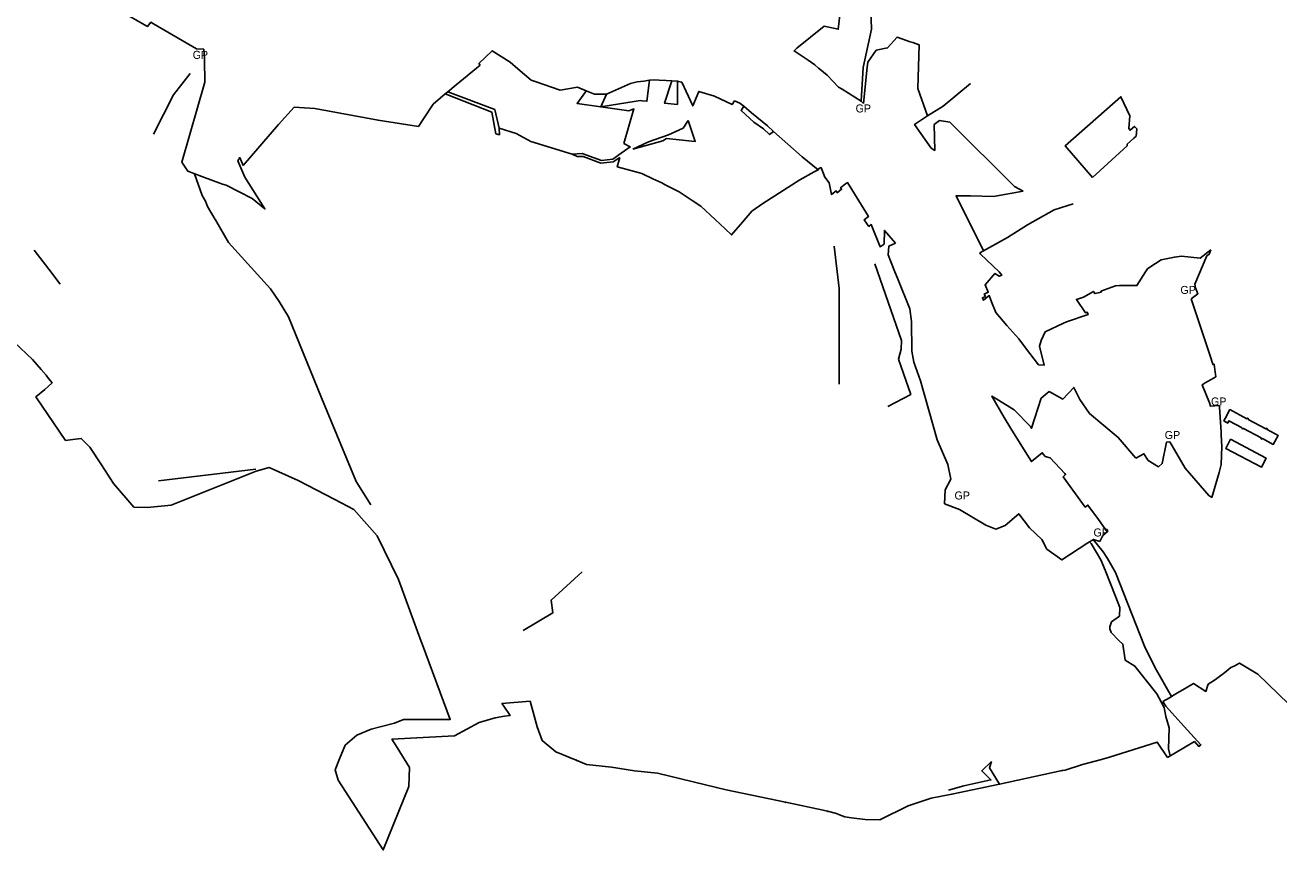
# Model space of a CAD drawing. Extents: x -617038 to -609441, y -1109294 to -1104285.
# Drawn here: x -612071 to -610504, y -1109294 to -1108263 of the extents above; entities that cross this region are included whole.
import ezdxf

# ---------------------------------------------------------------- set-up
doc = ezdxf.new("R2010")
doc.units = 0
for name, color, linetype in [('BOD_SET', 7, 'Continuous'), ('CESTY', 7, 'Continuous'), ('GRA_ZV', 7, 'Continuous'), ('LES_ZV', 7, 'Continuous'), ('Level 255', 7, 'Continuous'), ('OVNE_PRE', 7, 'Continuous'), ('OVNE_SET', 7, 'Continuous'), ('OVNI_PRE', 7, 'Continuous'), ('OVNI_SET', 7, 'Continuous'), ('VODA', 7, 'Continuous')]:
    doc.layers.add(name, color=color, linetype=linetype)

msp = doc.modelspace()

# ---------------------------------------------------------------- linework, layer by layer
at = {"layer": 'BOD_SET'}
for p, q in [((-612051.4, -1108693.2), (-612050.4, -1108694.2)), ((-612051.4, -1108694.2), (-612050.4, -1108693.2)), ((-612042.6, -1108714.4), (-612041.6, -1108715.4)), ((-612042.6, -1108715.4), (-612041.6, -1108714.4)), ((-612011.7, -1108780.8), (-612010.7, -1108781.8)), ((-612011.7, -1108781.8), (-612010.7, -1108780.8)), ((-611975.9, -1108812.4), (-611974.9, -1108813.4)), ((-611975.9, -1108813.4), (-611974.9, -1108812.4)), ((-611606.5, -1109165.6), (-611605.5, -1109166.6)), ((-611606.5, -1109166.6), (-611605.5, -1109165.6)), ((-611678.4, -1109179.9), (-611677.4, -1109180.9)), ((-611678.4, -1109180.9), (-611677.4, -1109179.9)), ((-611382.5, -1109181.5), (-611381.5, -1109182.5)), ((-611382.5, -1109182.5), (-611381.5, -1109181.5)), ((-610775.5, -1109194.6), (-610774.5, -1109195.6)), ((-610775.5, -1109195.6), (-610774.5, -1109194.6)), ((-610853.7, -1109211.3), (-610852.7, -1109212.3)), ((-610853.7, -1109212.3), (-610852.7, -1109211.3)), ((-611121.2, -1109234.1), (-611120.2, -1109235.1)), ((-611121.2, -1109235.1), (-611120.2, -1109234.1)), ((-611068.5, -1109245.4), (-611067.5, -1109246.4)), ((-611068.5, -1109246.4), (-611067.5, -1109245.4)), ((-611053.5, -1109249.7), (-611052.5, -1109250.7)), ((-611053.5, -1109250.7), (-611052.5, -1109249.7))]:
    msp.add_line(p, q, dxfattribs=at)
at = {"layer": 'CESTY'}
msp.add_lwpolyline([(-610736.2, -1108906.4), (-610723.8, -1108921.6), (-610718.2, -1108929.9), (-610708.3, -1108947.3), (-610671.9, -1109039.4), (-610658.6, -1109066.4), (-610638.2, -1109102.6)], dxfattribs=at)
at = {"layer": 'GRA_ZV'}
for points in [[(-611014.1, -1108244.1), (-611013.1, -1108268.3), (-611023.4, -1108316.4), (-611025.9, -1108358.5), (-611049.8, -1108343.5), (-611054.5, -1108340.8), (-611068.4, -1108326.1), (-611077.6, -1108318.3), (-611079.2, -1108317), (-611084.1, -1108312.9), (-611092.4, -1108307.2), (-611109.8, -1108295.5), (-611106.4, -1108292.3), (-611072.1, -1108264.7), (-611054.6, -1108268.6), (-611047, -1108202.2)], [(-611322.6, -1108411.3), (-611310, -1108368), (-611316.2, -1108370.4), (-611351.4, -1108365.5), (-611307.1, -1108358.5), (-611302.3, -1108357.7), (-611299.8, -1108357.9), (-611293.7, -1108358.4), (-611290.4, -1108332.2), (-611284.9, -1108331.9), (-611278.5, -1108332.2), (-611269.7, -1108332.7), (-611262.8, -1108333.1), (-611271.7, -1108360.9), (-611255.6, -1108362.5), (-611255.5, -1108333.5), (-611254.5, -1108333.7), (-611250.2, -1108334.6), (-611236.6, -1108364.4)], [(-611351.4, -1108365.5), (-611344.3, -1108349.8), (-611359.3, -1108349.6), (-611369.7, -1108345.4), (-611371.5, -1108348), (-611381.1, -1108361.3), (-611351.4, -1108365.5)], [(-611174.4, -1108509.8), (-611162.6, -1108495.9), (-611149, -1108486.4), (-611102.7, -1108456.8), (-611084.6, -1108446.8), (-611079.7, -1108444.1), (-611099.7, -1108427.8), (-611135.8, -1108396.1), (-611140.4, -1108400.1), (-611148.3, -1108393.1), (-611160, -1108384.5), (-611176.1, -1108369.9), (-611172.8, -1108364.5), (-611177.7, -1108360.9), (-611184.2, -1108358), (-611187.3, -1108362.7), (-611209.5, -1108352.3), (-611229, -1108346.3), (-611236.6, -1108364.4)], [(-611242.2, -1108382.7), (-611233.3, -1108408.6), (-611269.2, -1108405.2), (-611273.8, -1108408.1), (-611311.4, -1108418.4)], [(-611242.2, -1108382.7), (-611248.6, -1108392.3), (-611267, -1108400.4), (-611291.9, -1108409.4), (-611311.4, -1108418.4)], [(-611387.3, -1108424.7), (-611374.5, -1108423.7), (-611350.7, -1108432.7), (-611336.4, -1108430.7), (-611326, -1108423.4), (-611314.7, -1108415.5), (-611322.6, -1108411.3)], [(-611327.5, -1108428.9), (-611336.1, -1108434.4), (-611351.5, -1108435.9), (-611373.4, -1108427.4), (-611381, -1108427.5), (-611387.3, -1108424.7)], [(-611327.5, -1108428.9), (-611330.8, -1108440.4), (-611309.2, -1108446.4), (-611300.2, -1108448.9), (-611286.5, -1108455.3), (-611275.3, -1108460.6), (-611271.1, -1108463.1), (-611253.5, -1108471.9), (-611237.2, -1108482.5), (-611226.3, -1108489.7), (-611208.6, -1108506.1), (-611196, -1108517.9), (-611187.9, -1108525.6), (-611174.4, -1108509.8)]]:
    msp.add_lwpolyline(points, dxfattribs=at)
at = {"layer": 'LES_ZV'}
for p, q in [((-611322.6, -1108411.3), (-611310, -1108368)), ((-611438.8, -1108408.8), (-611387.3, -1108424.7)), ((-611053.6, -1108592.5), (-611059.6, -1108539.4)), ((-611053.7, -1108712.1), (-611053.6, -1108592.5)), ((-611904.2, -1108832.8), (-611782.7, -1108818.5))]:
    msp.add_line(p, q, dxfattribs=at)
for points in [[(-611864.7, -1108324), (-611885.2, -1108350.4), (-611910.6, -1108399.5)], [(-610943.3, -1108376.7), (-610923.7, -1108364.6), (-610889.3, -1108336.4)], [(-611545.9, -1108349.4), (-611487.6, -1108372), (-611482.5, -1108399.1), (-611478.1, -1108400.3), (-611478.4, -1108392.3), (-611483.9, -1108369), (-611542.5, -1108346.6)], [(-611310, -1108368), (-611316.2, -1108370.4), (-611351.4, -1108365.5)], [(-611478.4, -1108392.3), (-611457, -1108398.6), (-611438.8, -1108408.8)], [(-610873.1, -1108545.5), (-610843.3, -1108528.7), (-610818, -1108513.1), (-610784.8, -1108494.2), (-610761.3, -1108486.8)], [(-612059.7, -1108544.5), (-612041.4, -1108568.5), (-612027.2, -1108587)], [(-611008.8, -1108561.5), (-610975.8, -1108657.6), (-610976.1, -1108668.4), (-610979.3, -1108680.9), (-610964, -1108724.9), (-610992.6, -1108739.8)], [(-611448.3, -1109019.9), (-611411.4, -1108998), (-611413.5, -1108982), (-611374.7, -1108946.7)], [(-610917, -1109219.6), (-610897.6, -1109214.1), (-610864, -1109206.7), (-610875.4, -1109195.4), (-610863.3, -1109183.6)], [(-610863.3, -1109183.6), (-610865.6, -1109191.4), (-610853.2, -1109211.8)]]:
    msp.add_lwpolyline(points, dxfattribs=at)
at = {"layer": 'Level 255'}
for p, q in [((-610843.3, -1108528.7), (-610843.3, -1108528.7)), ((-610735.6, -1108906), (-610735.6, -1108906))]:
    msp.add_line(p, q, dxfattribs=at)
at = {"layer": 'OVNE_PRE'}
for points in [[(-612084.5, -1108659.6), (-612061.5, -1108681.4), (-612050.9, -1108693.7), (-612044.7, -1108700.9), (-612041.8, -1108705.1), (-612037.2, -1108710.3), (-612042.1, -1108714.9), (-612046.1, -1108718.8), (-612057.4, -1108727.9), (-612020.3, -1108782.5), (-612011.2, -1108781.3), (-612000.6, -1108779.9), (-611989.8, -1108790.6), (-611975.4, -1108812.9), (-611960.2, -1108836.4)], [(-611960.2, -1108836.4), (-611934.8, -1108865.7), (-611918.1, -1108866.1), (-611888.5, -1108863.1), (-611781.9, -1108820.6), (-611765.8, -1108816.3), (-611729.5, -1108832.3), (-611683.8, -1108856.1), (-611660, -1108868.5), (-611630.8, -1108901.7), (-611604.3, -1108956.4), (-611575.7, -1109033.6), (-611574.2, -1109037.7), (-611539.6, -1109131), (-611585.8, -1109131.2), (-611598.1, -1109131.3), (-611609.3, -1109135.7), (-611625.6, -1109139.9), (-611638.2, -1109143.1), (-611656.2, -1109150.6), (-611670.9, -1109163.4)], [(-611670.9, -1109163.4), (-611677.9, -1109180.4), (-611683.5, -1109194.1), (-611679.8, -1109206.8), (-611623.3, -1109294.2), (-611591.4, -1109214.7), (-611590.4, -1109191.1), (-611606, -1109166.1), (-611612.4, -1109155.9), (-611534.2, -1109151.4), (-611503.5, -1109134.9), (-611483.6, -1109128.9), (-611471.7, -1109127.1), (-611464.8, -1109126.2), (-611472.6, -1109114.6), (-611474.9, -1109111.2), (-611439.8, -1109108.3), (-611431.1, -1109140.4), (-611424.8, -1109157.6), (-611407.7, -1109171.5), (-611382, -1109182), (-611369.3, -1109187.2), (-611337.9, -1109190.8), (-611309.3, -1109195.4), (-611280.5, -1109198.4), (-611206.9, -1109216.3), (-611194.8, -1109218.9), (-611120.7, -1109234.6), (-611073.5, -1109244.6), (-611068, -1109245.9), (-611057, -1109248.5), (-611053, -1109250.2), (-611046.5, -1109253), (-611038.1, -1109254), (-611021.2, -1109256.1), (-611002.9, -1109256.4), (-610967.3, -1109239.1), (-610938.6, -1109229.6), (-610912.7, -1109224.5), (-610853.2, -1109211.8), (-610775, -1109195.1), (-610771.2, -1109194.3), (-610749.6, -1109187.6), (-610725.5, -1109181.3), (-610715.6, -1109178.2), (-610656, -1109159.3), (-610643.3, -1109178.8)]]:
    msp.add_lwpolyline(points, dxfattribs=at)
at = {"layer": 'OVNE_SET'}
msp.add_line((-610649, -1109108.7), (-610640.8, -1109104.2), dxfattribs=at)
for points in [[(-610444.9, -1109093.9), (-610447.8, -1109098), (-610470.6, -1109100.9), (-610486.2, -1109108.7), (-610492.1, -1109111.6), (-610530.2, -1109074.7), (-610553.1, -1109060.6), (-610558, -1109063.4), (-610559.1, -1109063.9), (-610562, -1109065.2), (-610564, -1109066.1), (-610571.5, -1109072.5), (-610583.4, -1109081), (-610592.3, -1109087.1), (-610595.2, -1109096), (-610610.8, -1109086.2), (-610621.8, -1109092.7), (-610632.7, -1109099.1), (-610635.1, -1109100.5), (-610640.8, -1109104.2)], [(-610643.3, -1109178.8), (-610609.6, -1109158.7), (-610604.2, -1109164.7), (-610601.5, -1109162.7), (-610626.6, -1109135.4), (-610645.3, -1109114.4), (-610649, -1109108.7)]]:
    msp.add_lwpolyline(points, dxfattribs=at)
at = {"layer": 'OVNI_PRE'}
for p, q in [((-611847.7, -1108293.3), (-611846.8, -1108305.5)), ((-610834.9, -1108744.1), (-610854.3, -1108732.2))]:
    msp.add_line(p, q, dxfattribs=at)
for points in [[(-610955.4, -1108342.7), (-610953.5, -1108288.1), (-610961.6, -1108285.2), (-610965, -1108284.1)], [(-610571.2, -1108755.1), (-610565.2, -1108743.9), (-610544, -1108755.3), (-610543.5, -1108754.5), (-610542, -1108755.3), (-610542.4, -1108756.1), (-610520.3, -1108767.9), (-610519.9, -1108767.1), (-610518.3, -1108768), (-610518.7, -1108768.8), (-610505.1, -1108776.1), (-610511.1, -1108787.3), (-610524.7, -1108780), (-610525.1, -1108780.8), (-610526.7, -1108779.9), (-610526.3, -1108779.1), (-610548.3, -1108767.4), (-610548.7, -1108768.1), (-610550.3, -1108767.3), (-610549.9, -1108766.5)], [(-610564.5, -1108781), (-610519.8, -1108804.6), (-610525.8, -1108815.9), (-610570.4, -1108792.3), (-610564.5, -1108781)]]:
    msp.add_lwpolyline(points, dxfattribs=at)
at = {"layer": 'OVNI_SET'}
for p, q in [((-611856.8, -1108293.1), (-611847.7, -1108293.3)), ((-611846.7, -1108306.7), (-611846.8, -1108305.5)), ((-611504, -1108311.5), (-611502.2, -1108313.6)), ((-611290.4, -1108332.2), (-611297.7, -1108333.2)), ((-611262.8, -1108333.1), (-611255.5, -1108333.5)), ((-610955.4, -1108342.7), (-610943.3, -1108376.7)), ((-611025.9, -1108358.5), (-611023.1, -1108361.1)), ((-611579.1, -1108390), (-611572.8, -1108380.5)), ((-610727.6, -1108908.5), (-610723.9, -1108901.1))]:
    msp.add_line(p, q, dxfattribs=at)
for points in [[(-611025.9, -1108358.5), (-611049.8, -1108343.5), (-611054.5, -1108340.8), (-611068.4, -1108326.1), (-611077.6, -1108318.3), (-611079.2, -1108317), (-611084.1, -1108312.9), (-611092.4, -1108307.2), (-611109.8, -1108295.5), (-611106.4, -1108292.3), (-611072.1, -1108264.7), (-611054.6, -1108268.6), (-611047, -1108202.2), (-611070.5, -1108190.5), (-611071.8, -1108186.4), (-611074.4, -1108181.6), (-611106.1, -1108200), (-611131.8, -1108202.4), (-611178.6, -1108190.1), (-611187.6, -1108174.1), (-611192.3, -1108171.4), (-611220.6, -1108154.8)], [(-612017.1, -1108209.8), (-611980, -1108229.3), (-611918, -1108265.2), (-611913.7, -1108259.8), (-611910.3, -1108261.8), (-611856.8, -1108293.1)], [(-611007.1, -1108294.7), (-610993, -1108291.8), (-610981.2, -1108278.4), (-610965, -1108284.1)], [(-611846.7, -1108306.7), (-611846.4, -1108334.6), (-611874.8, -1108434.6), (-611867.5, -1108446), (-611849.8, -1108452.4), (-611824.1, -1108462.2)], [(-611504, -1108311.5), (-611487.3, -1108295.3), (-611464.7, -1108309.5), (-611455, -1108318), (-611438.5, -1108332.2), (-611433.6, -1108333.9), (-611402.3, -1108344.5), (-611380.7, -1108340.9), (-611369.7, -1108345.4)], [(-611023.1, -1108361.1), (-611018.7, -1108316.1), (-611017.9, -1108309.6), (-611007.1, -1108294.7)], [(-611572.8, -1108380.5), (-611560.8, -1108362.3), (-611545.9, -1108349.4), (-611542.5, -1108346.6), (-611532.2, -1108338.1), (-611502.2, -1108313.6)], [(-611369.7, -1108345.4), (-611359.3, -1108349.6), (-611344.3, -1108349.8), (-611314.2, -1108336.4), (-611305.9, -1108334.3), (-611297.7, -1108333.2)], [(-611290.4, -1108332.2), (-611284.9, -1108331.9), (-611278.5, -1108332.2), (-611269.7, -1108332.7), (-611262.8, -1108333.1)], [(-611255.5, -1108333.5), (-611254.5, -1108333.7), (-611250.2, -1108334.6), (-611236.6, -1108364.4), (-611229, -1108346.3), (-611209.5, -1108352.3), (-611187.3, -1108362.7), (-611184.2, -1108358), (-611177.7, -1108360.9), (-611172.8, -1108364.5)], [(-610736.9, -1108453.7), (-610771.2, -1108414.4), (-610701.5, -1108352.9), (-610690.1, -1108376.7), (-610691.7, -1108392.7), (-610689.9, -1108394.8), (-610684.4, -1108390), (-610681.7, -1108393), (-610682.2, -1108402), (-610685.3, -1108404.7), (-610693.5, -1108412), (-610693.7, -1108414.1), (-610736.9, -1108453.7)], [(-611798.4, -1108438.6), (-611754, -1108387.4), (-611734.7, -1108365.8)], [(-611734.7, -1108365.8), (-611708.7, -1108367.7), (-611629.8, -1108382.3), (-611579.1, -1108390)], [(-611172.8, -1108364.5), (-611162.9, -1108373.1), (-611143, -1108389.1), (-611135.8, -1108396.1)], [(-610823.4, -1108470.9), (-610834.5, -1108464.9), (-610915.2, -1108384.8), (-610928.2, -1108382.7), (-610935, -1108387.6), (-610934.1, -1108419.9), (-610938.5, -1108417), (-610959.3, -1108387.5), (-610949.4, -1108380.9), (-610943.3, -1108376.7)], [(-611079.7, -1108444.1), (-611099.7, -1108427.8), (-611135.8, -1108396.1)], [(-611824.1, -1108462.2), (-611819.6, -1108463.5), (-611787.3, -1108480.1), (-611771.1, -1108493.1), (-611796.1, -1108453.3), (-611805.1, -1108433.1), (-611802.6, -1108428.9), (-611798.4, -1108438.6)], [(-610983.1, -1108535.8), (-610996.9, -1108519.9), (-610997.2, -1108537.1), (-611002.4, -1108540.4), (-611013.4, -1108512.6), (-611016.3, -1108514.9), (-611022.5, -1108506.9), (-611017, -1108502.6), (-611020.4, -1108497.1), (-611043.1, -1108460.1), (-611045.5, -1108461.9), (-611051.8, -1108466.6), (-611050.5, -1108468.5), (-611056, -1108472.8), (-611057.2, -1108470.6), (-611063.2, -1108475), (-611065.9, -1108460.6), (-611071.3, -1108453.5), (-611075.6, -1108442.6), (-611076.4, -1108441.4), (-611079.3, -1108443.1), (-611079, -1108443.7), (-611079.7, -1108444.1)], [(-610823.4, -1108470.9), (-610860.7, -1108477.5), (-610889.4, -1108476.9), (-610907.5, -1108476.5), (-610873.1, -1108545.5)], [(-610983.1, -1108535.8), (-610991.6, -1108539.7), (-610992.1, -1108550.6)], [(-610992.1, -1108550.6), (-610989.2, -1108557.9), (-610983.8, -1108571.5), (-610980.6, -1108579.5), (-610965.3, -1108618.1), (-610963.2, -1108633.6), (-610962.7, -1108671), (-610960.2, -1108684.5), (-610951.9, -1108708.1), (-610931.2, -1108781.8), (-610917.6, -1108812.4)], [(-610873.1, -1108545.5), (-610877.7, -1108548.1), (-610876.8, -1108549.7), (-610853.4, -1108571.8), (-610850.3, -1108576), (-610853.4, -1108577.3), (-610859, -1108573.6), (-610871.2, -1108588.1), (-610867.2, -1108597.1), (-610872.2, -1108599.5), (-610870.8, -1108602.3), (-610874.6, -1108604.1), (-610873.1, -1108607.2), (-610866, -1108601.4), (-610863, -1108609.2), (-610857.8, -1108622.7), (-610843.9, -1108638.6), (-610829.2, -1108655.5), (-610820.7, -1108666.6), (-610804.4, -1108688), (-610797.3, -1108688.3), (-610803.3, -1108664.5), (-610801, -1108657.6), (-610796.2, -1108646.8), (-610773.3, -1108635.8)], [(-610725.9, -1108597.2), (-610726.4, -1108595.9), (-610708.1, -1108589), (-610703.4, -1108588.9), (-610681.5, -1108588.8), (-610670.8, -1108571.7), (-610668.1, -1108567.8), (-610665.1, -1108565.8), (-610651.3, -1108556.7), (-610634.5, -1108553.2), (-610625.8, -1108552.3), (-610602.5, -1108554.6), (-610589.2, -1108544.3)], [(-610609.1, -1108587.2), (-610594, -1108551.7), (-610591.3, -1108549.7), (-610589.2, -1108544.3)], [(-610613.7, -1108605.5), (-610605.4, -1108599.2), (-610608.1, -1108591.5), (-610609.1, -1108587.2)], [(-610773.3, -1108635.8), (-610769.5, -1108634.1), (-610742.5, -1108625.1), (-610743.6, -1108622.1), (-610745.8, -1108622.9), (-610757, -1108606.2), (-610748.1, -1108603.2), (-610735.8, -1108596.1), (-610734, -1108598.9), (-610725.9, -1108597.2)], [(-610613.7, -1108605.5), (-610597.6, -1108654.1), (-610590.1, -1108676.5), (-610586.4, -1108686.9), (-610586, -1108687.9), (-610584.9, -1108687.2), (-610583.6, -1108696.9), (-610583.3, -1108699.5), (-610582.9, -1108702.9), (-610588.6, -1108706.2), (-610596.3, -1108710.6), (-610599.7, -1108712.8), (-610590.9, -1108735.6)], [(-610854.3, -1108732.2), (-610862.8, -1108727.1), (-610847.3, -1108753.8), (-610839.2, -1108767.3), (-610821.2, -1108796.4), (-610813.3, -1108808.8), (-610799.8, -1108797.8), (-610796, -1108802.6), (-610789.8, -1108804)], [(-610790.9, -1108721.4), (-610800.9, -1108729.6), (-610813.1, -1108767.1), (-610814.5, -1108764.8), (-610834.9, -1108744.1)], [(-610790.9, -1108721.4), (-610773.9, -1108730.8), (-610760.3, -1108716.2), (-610752.9, -1108731.3), (-610740.7, -1108748.7), (-610704.8, -1108778.7), (-610682.8, -1108804.7)], [(-610588, -1108853.6), (-610578.8, -1108822.5), (-610576.3, -1108812.3), (-610575.4, -1108789.9), (-610576.1, -1108775.6), (-610576.3, -1108771.9), (-610578.3, -1108740.7), (-610578.4, -1108738.8), (-610589.5, -1108739.7), (-610590.9, -1108735.6)], [(-610549.9, -1108766.5), (-610566.4, -1108757.7), (-610568, -1108760.7), (-610572.8, -1108758.1), (-610571.2, -1108755.1)], [(-610682.8, -1108804.7), (-610672.7, -1108799.1), (-610667.2, -1108807.4), (-610654.5, -1108815.3), (-610649.7, -1108811.3), (-610644.3, -1108784.5), (-610640.5, -1108784.3)], [(-610640.5, -1108784.3), (-610621.3, -1108817.2), (-610591.7, -1108851.3), (-610588, -1108853.6)], [(-610723.9, -1108901.1), (-610718.5, -1108896.7), (-610729.5, -1108881.1), (-610742.7, -1108863.1), (-610746.1, -1108865.6), (-610773.7, -1108827.9), (-610770.6, -1108825.1), (-610771.6, -1108823.7), (-610789.8, -1108804)], [(-610917.6, -1108812.4), (-610914, -1108831), (-610921, -1108844), (-610921.8, -1108861.5)], [(-610921.8, -1108861.5), (-610903, -1108868.8), (-610870.4, -1108888.4), (-610857.9, -1108893.1), (-610846, -1108888.6), (-610829.2, -1108874), (-610815.8, -1108891.5), (-610800.3, -1108906.1), (-610793.9, -1108918.1), (-610775.3, -1108931.8), (-610742.6, -1108910.5), (-610735.6, -1108906), (-610727.6, -1108908.5)]]:
    msp.add_lwpolyline(points, dxfattribs=at)
at = {"layer": 'VODA'}
for points in [[(-611638.9, -1108862.7), (-611657.2, -1108833.8), (-611700.3, -1108729), (-611741.8, -1108628.1), (-611753.2, -1108608.6), (-611764, -1108592.9), (-611816.7, -1108535.2), (-611832.8, -1108506.8), (-611833.2, -1108506.3), (-611843.1, -1108490), (-611845.4, -1108483.2), (-611849.7, -1108476.3), (-611859.3, -1108449)], [(-610740.5, -1108909.1), (-610738.6, -1108911.3), (-610731.8, -1108922.4), (-610726.5, -1108931.5), (-610721, -1108944.6), (-610707.9, -1108978.1), (-610702.8, -1108991.2), (-610703.4, -1109002), (-610713.4, -1109009), (-610715.3, -1109015.2), (-610715.3, -1109017.9), (-610713.8, -1109022.4), (-610704, -1109032.6), (-610699, -1109037), (-610696, -1109057.2), (-610683.9, -1109064.4), (-610656.5, -1109099.2), (-610647.4, -1109116.2), (-610645.1, -1109127.4), (-610641.2, -1109141.7), (-610642, -1109168), (-610639.7, -1109176.6)]]:
    msp.add_lwpolyline(points, dxfattribs=at)

# ---------------------------------------------------------------- texts
at = {"layer": 'Level 255'}
msp.add_text('GP', height=10, dxfattribs=at).set_placement((-611033, -1108372.5))
at = {"layer": 'OVNE_SET'}
for p in [(-611861.5, -1108305.5), (-610627.1, -1108599.3), (-610588.9, -1108738.7), (-610646.7, -1108780.6), (-610909.4, -1108856.2), (-610735.7, -1108902.4)]:
    msp.add_text('GP', height=10, dxfattribs=at).set_placement(p)

doc.saveas('drawing.dxf')
